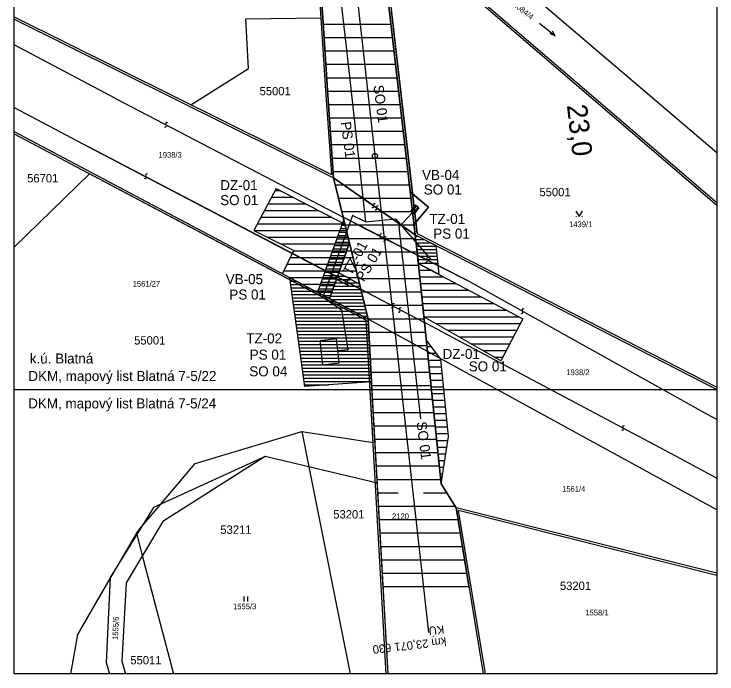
# Model space of a CAD drawing. Extents: x -792659 to -786947, y -1118170 to -1109641.
# Drawn here: x -792658.7 to -792553.7, y -1110542.5 to -1110443.9 of the extents above; entities that cross this region are included whole.
import ezdxf

# ---------------------------------------------------------------- set-up
doc = ezdxf.new("R2010")
doc.units = 0
doc.layers.add('1', color=7, linetype='Continuous')

# ---------------------------------------------------------------- blocks, each defined once
blk = doc.blocks.new('Z31400')
at = {"layer": '1'}
for p, q in [((-1, 1.5), (0, 0)), ((-1, 0), (-0.8, 0)), ((0, 0), (1, 1.5)), ((0.8, 0), (1, 0))]:
    blk.add_line(p, q, dxfattribs=at)
blk = doc.blocks.new('Z8021')
at = {"layer": '1'}
for p, q in [((-3, 0), (3, 0)), ((3, 0), (1.5, 0.5)), ((3, 0), (1.5, -0.5))]:
    blk.add_line(p, q, dxfattribs=at)
blk = doc.blocks.new('Z30602')
at = {"layer": '1'}
for p, q in [((-0.5, 0), (-0.5, 1.5)), ((0.5, 1.5), (0.5, 0))]:
    blk.add_line(p, q, dxfattribs=at)

msp = doc.modelspace()

# ---------------------------------------------------------------- linework, layer by layer
at = {"layer": '1'}
for p, q in [((-792613.96, -1110405.45), (-792608.61, -1110452.76)), ((-792614.67, -1110416.72), (-792612.15, -1110455.3)), ((-792614.37, -1110416.71), (-792611.85, -1110455.28)), ((-792605.76, -1110415.98), (-792598.74, -1110476.89)), ((-792598.74, -1110476.89), (-792605.76, -1110415.98)), ((-792598.74, -1110476.89), (-792605.76, -1110415.98)), ((-792605.39, -1110416.55), (-792598.46, -1110476.7)), ((-792591.51, -1110432.33), (-792553.68, -1110464.6)), ((-792597.93, -1110434.54), (-792553.68, -1110472.43)), ((-792597.68, -1110434.36), (-792553.68, -1110472.03)), ((-792598.46, -1110476.7), (-792602.29, -1110443.46)), ((-792598.46, -1110476.7), (-792602.29, -1110443.46)), ((-792658.68, -1110444.34), (-792611.28, -1110467.89)), ((-792658.68, -1110444.68), (-792610.94, -1110468.39)), ((-792612.47, -1110445.41), (-792602.37, -1110445.41)), ((-792612.34, -1110447.41), (-792602.14, -1110447.41)), ((-792643.45, -1110456.57), (-792658.68, -1110448.5)), ((-792612.2, -1110449.41), (-792601.91, -1110449.41)), ((-792612.07, -1110451.41), (-792601.68, -1110451.41)), ((-792611.94, -1110453.41), (-792601.45, -1110453.41)), ((-792608.61, -1110452.76), (-792606.17, -1110474.95)), ((-792612.15, -1110455.3), (-792611.28, -1110467.89)), ((-792611.85, -1110455.28), (-792610.94, -1110468.39)), ((-792611.8, -1110455.41), (-792601.22, -1110455.41)), ((-792643.45, -1110456.57), (-792609.51, -1110474.26)), ((-792658.68, -1110457.84), (-792647.57, -1110463.72)), ((-792611.67, -1110457.41), (-792600.98, -1110457.41)), ((-792611.54, -1110459.41), (-792600.76, -1110459.41)), ((-792658.68, -1110461.46), (-792605.8, -1110489.46)), ((-792658.68, -1110461.8), (-792606.09, -1110489.65)), ((-792611.41, -1110461.41), (-792605.1, -1110461.41)), ((-792605.73, -1110461.41), (-792600.52, -1110461.41)), ((-792647.57, -1110463.72), (-792608.66, -1110484.08)), ((-792606.89, -1110485.01), (-792647.57, -1110463.72)), ((-792611.27, -1110463.41), (-792600.29, -1110463.41)), ((-792611.14, -1110465.41), (-792600.06, -1110465.41)), ((-792658.68, -1110478.72), (-792647.43, -1110467.76)), ((-792606.09, -1110489.65), (-792647.43, -1110467.76)), ((-792611.01, -1110467.41), (-792599.83, -1110467.41)), ((-792598.74, -1110476.89), (-792610.94, -1110468.39)), ((-792610.94, -1110468.39), (-792609.51, -1110474.26)), ((-792610.94, -1110468.39), (-792598.74, -1110476.89)), ((-792610.94, -1110468.39), (-792609.51, -1110474.26)), ((-792610.69, -1110469.41), (-792599.6, -1110469.41)), ((-792619.53, -1110469.94), (-792622.88, -1110476.25)), ((-792619.7, -1110470.25), (-792618.92, -1110470.25)), ((-792619.53, -1110469.94), (-792609.26, -1110475.29)), ((-792596.78, -1110472.75), (-792599.48, -1110470.49)), ((-792620.23, -1110471.25), (-792617, -1110471.25)), ((-792610.2, -1110471.41), (-792599.37, -1110471.41)), ((-792620.76, -1110472.25), (-792615.09, -1110472.25)), ((-792598.7, -1110472.45), (-792599.47, -1110473.37)), ((-792598.7, -1110472.45), (-792599.47, -1110473.37)), ((-792599.29, -1110472.15), (-792599.29, -1110472.15)), ((-792598.58, -1110472.54), (-792599.22, -1110473.31)), ((-792598.58, -1110472.54), (-792599.22, -1110473.31)), ((-792598.19, -1110472.87), (-792598.7, -1110472.45)), ((-792598.19, -1110472.87), (-792598.7, -1110472.45)), ((-792621.29, -1110473.25), (-792613.17, -1110473.25)), ((-792609.72, -1110473.41), (-792599.14, -1110473.41)), ((-792601.15, -1110475.7), (-792599.22, -1110473.58)), ((-792599.47, -1110473.37), (-792598.96, -1110473.79)), ((-792599.47, -1110473.37), (-792598.96, -1110473.79)), ((-792599.22, -1110473.31), (-792598.95, -1110473.54)), ((-792599.22, -1110473.31), (-792598.95, -1110473.54)), ((-792598.96, -1110473.79), (-792598.19, -1110472.87)), ((-792598.19, -1110472.87), (-792598.96, -1110473.79)), ((-792598.95, -1110473.54), (-792598.31, -1110472.78)), ((-792598.31, -1110472.78), (-792598.95, -1110473.54)), ((-792598.92, -1110475.3), (-792596.78, -1110472.75)), ((-792621.82, -1110474.25), (-792611.25, -1110474.25)), ((-792609.44, -1110474.53), (-792613.35, -1110485.46)), ((-792608.13, -1110474.01), (-792611.42, -1110483.05)), ((-792606.67, -1110475.74), (-792609.51, -1110474.26)), ((-792609.51, -1110474.26), (-792606.89, -1110485.01)), ((-792598.42, -1110479.91), (-792609.51, -1110474.26)), ((-792609.51, -1110474.26), (-792606.89, -1110485.01)), ((-792606.17, -1110474.95), (-792608.13, -1110474.01)), ((-792606.17, -1110474.95), (-792601.71, -1110474.49)), ((-792601.71, -1110474.49), (-792596.44, -1110480.58)), ((-792622.35, -1110475.25), (-792609.33, -1110475.25)), ((-792609.77, -1110475.46), (-792609.21, -1110475.46)), ((-792609.59, -1110474.96), (-792609.33, -1110474.96)), ((-792609.23, -1110475.41), (-792598.91, -1110475.41)), ((-792606.67, -1110475.74), (-792598.42, -1110479.91)), ((-792597.92, -1110504.39), (-792601.15, -1110475.7)), ((-792622.88, -1110476.25), (-792616.88, -1110479.22)), ((-792622.88, -1110476.25), (-792609.03, -1110476.25)), ((-792610.13, -1110476.46), (-792608.97, -1110476.46)), ((-792609.95, -1110475.96), (-792609.09, -1110475.96)), ((-792598.46, -1110476.7), (-792553.68, -1110499.62)), ((-792620.86, -1110477.25), (-792608.78, -1110477.25)), ((-792610.49, -1110477.46), (-792608.73, -1110477.46)), ((-792610.31, -1110476.96), (-792608.85, -1110476.96)), ((-792608.74, -1110477.41), (-792598.69, -1110477.41)), ((-792598.74, -1110476.89), (-792598.42, -1110479.91)), ((-792598.74, -1110476.89), (-792553.68, -1110499.96)), ((-792598.42, -1110479.91), (-792598.74, -1110476.89)), ((-792598.74, -1110476.89), (-792595.67, -1110478.46)), ((-792598.72, -1110477.09), (-792598.35, -1110477.09)), ((-792598.67, -1110477.59), (-792597.37, -1110477.59)), ((-792618.84, -1110478.25), (-792608.54, -1110478.25)), ((-792610.85, -1110478.46), (-792608.72, -1110478.46)), ((-792610.67, -1110477.96), (-792608.6, -1110477.96)), ((-792608.58, -1110478.06), (-792610.18, -1110482.54)), ((-792598.61, -1110478.09), (-792596.39, -1110478.09)), ((-792598.56, -1110478.59), (-792595.66, -1110478.59)), ((-792618.57, -1110482.7), (-792616.88, -1110479.22)), ((-792616.9, -1110479.25), (-792608.3, -1110479.25)), ((-792611.38, -1110479.96), (-792609.26, -1110479.96)), ((-792611.2, -1110479.46), (-792609.08, -1110479.46)), ((-792611.03, -1110478.96), (-792608.9, -1110478.96)), ((-792608.26, -1110479.41), (-792598.48, -1110479.41)), ((-792598.51, -1110479.09), (-792595.6, -1110479.09)), ((-792598.46, -1110479.59), (-792595.55, -1110479.59)), ((-792591.02, -1110483.65), (-792598.42, -1110479.91)), ((-792598.42, -1110479.91), (-792597.37, -1110489.98)), ((-792597.37, -1110489.98), (-792598.42, -1110479.91)), ((-792598.42, -1110479.91), (-792591.02, -1110483.65)), ((-792617.39, -1110480.25), (-792608.05, -1110480.25)), ((-792611.74, -1110480.96), (-792609.61, -1110480.96)), ((-792611.56, -1110480.46), (-792609.44, -1110480.46)), ((-792598.41, -1110480.09), (-792595.49, -1110480.09)), ((-792598.35, -1110480.59), (-792595.44, -1110480.59)), ((-792617.87, -1110481.25), (-792607.81, -1110481.25)), ((-792612.1, -1110481.96), (-792609.97, -1110481.96)), ((-792611.92, -1110481.46), (-792609.79, -1110481.46)), ((-792607.77, -1110481.41), (-792598.27, -1110481.41)), ((-792598.3, -1110481.09), (-792595.38, -1110481.09)), ((-792598.29, -1110481.14), (-792582.67, -1110489.42)), ((-792618.36, -1110482.25), (-792607.57, -1110482.25)), ((-792611.42, -1110483.05), (-792612.54, -1110486.17)), ((-792612.46, -1110482.96), (-792610.33, -1110482.96)), ((-792612.28, -1110482.46), (-792610.15, -1110482.46)), ((-792610.18, -1110482.54), (-792611.56, -1110486.41)), ((-792611.42, -1110483.05), (-792608.74, -1110484.47)), ((-792610.36, -1110483.04), (-792609.27, -1110483.04)), ((-792607.08, -1110484.25), (-792610.18, -1110482.54)), ((-792610.18, -1110482.54), (-792610.18, -1110482.54)), ((-792598.19, -1110482.14), (-792596.4, -1110482.14)), ((-792598.08, -1110483.14), (-792594.51, -1110483.14)), ((-792617.52, -1110483.25), (-792610.43, -1110483.25)), ((-792615.26, -1110499.53), (-792617.47, -1110483.28)), ((-792617.47, -1110483.28), (-792617.47, -1110483.28)), ((-792605.8, -1110489.46), (-792617.47, -1110483.28)), ((-792617.4, -1110483.78), (-792616.53, -1110483.78)), ((-792612.81, -1110483.96), (-792610.69, -1110483.96)), ((-792612.64, -1110483.46), (-792610.51, -1110483.46)), ((-792610.71, -1110484.04), (-792607.46, -1110484.04)), ((-792610.54, -1110483.54), (-792608.37, -1110483.54)), ((-792608.89, -1110483.25), (-792607.32, -1110483.25)), ((-792608.66, -1110484.08), (-792606.89, -1110485.01)), ((-792607.28, -1110483.41), (-792598.06, -1110483.41)), ((-792597.98, -1110484.14), (-792592.63, -1110484.14)), ((-792555.17, -1110503.69), (-792591.02, -1110483.65)), ((-792617.33, -1110484.28), (-792615.58, -1110484.28)), ((-792617.27, -1110484.78), (-792614.64, -1110484.78)), ((-792615.63, -1110484.25), (-792610.79, -1110484.25)), ((-792613.17, -1110484.96), (-792611.04, -1110484.96)), ((-792612.99, -1110484.46), (-792610.86, -1110484.46)), ((-792611.07, -1110485.04), (-792606.89, -1110485.04)), ((-792610.89, -1110484.54), (-792607.01, -1110484.54)), ((-792606.89, -1110485.01), (-792597.37, -1110489.98)), ((-792605.8, -1110489.46), (-792606.89, -1110485.01)), ((-792605.8, -1110489.46), (-792606.89, -1110485.01)), ((-792606.89, -1110485.01), (-792597.37, -1110489.98)), ((-792597.87, -1110485.14), (-792590.75, -1110485.14)), ((-792617.2, -1110485.28), (-792613.69, -1110485.28)), ((-792617.13, -1110485.78), (-792612.75, -1110485.78)), ((-792617.06, -1110486.28), (-792611.81, -1110486.28)), ((-792613.75, -1110485.25), (-792611.15, -1110485.25)), ((-792613.35, -1110485.46), (-792611.22, -1110485.46)), ((-792612.54, -1110486.17), (-792609.77, -1110488.09)), ((-792612.41, -1110485.96), (-792611.4, -1110485.96)), ((-792611.86, -1110486.25), (-792611.5, -1110486.25)), ((-792611.43, -1110486.04), (-792606.64, -1110486.04)), ((-792611.25, -1110485.54), (-792606.76, -1110485.54)), ((-792606.79, -1110485.41), (-792597.85, -1110485.41)), ((-792597.77, -1110486.14), (-792588.86, -1110486.14)), ((-792616.99, -1110486.78), (-792610.86, -1110486.78)), ((-792616.93, -1110487.28), (-792609.92, -1110487.28)), ((-792611.31, -1110486.54), (-792606.52, -1110486.54)), ((-792610.37, -1110487.04), (-792606.4, -1110487.04)), ((-792597.67, -1110487.14), (-792586.98, -1110487.14)), ((-792616.86, -1110487.78), (-792608.97, -1110487.78)), ((-792616.79, -1110488.28), (-792608.03, -1110488.28)), ((-792609.77, -1110488.09), (-792608.83, -1110494.04)), ((-792609.43, -1110487.54), (-792606.27, -1110487.54)), ((-792608.48, -1110488.04), (-792606.15, -1110488.04)), ((-792606.3, -1110487.41), (-792597.64, -1110487.41)), ((-792597.56, -1110488.14), (-792585.09, -1110488.14)), ((-792616.72, -1110488.78), (-792607.08, -1110488.78)), ((-792616.65, -1110489.28), (-792606.14, -1110489.28)), ((-792607.54, -1110488.54), (-792606.03, -1110488.54)), ((-792606.59, -1110489.04), (-792605.9, -1110489.04)), ((-792605.81, -1110489.41), (-792597.43, -1110489.41)), ((-792585.96, -1110495.68), (-792597.46, -1110489.11)), ((-792597.42, -1110489.14), (-792583.21, -1110489.14)), ((-792582.67, -1110489.42), (-792585.96, -1110495.68)), ((-792616.59, -1110489.78), (-792605.78, -1110489.78)), ((-792616.52, -1110490.28), (-792605.75, -1110490.28)), ((-792603.09, -1110542.47), (-792606.09, -1110489.65)), ((-792605.05, -1110507.9), (-792606.09, -1110489.65)), ((-792596.92, -1110494.31), (-792605.8, -1110489.46)), ((-792603.52, -1110529.61), (-792605.8, -1110489.46)), ((-792605.27, -1110498.84), (-792605.8, -1110489.46)), ((-792596.92, -1110494.31), (-792605.8, -1110489.46)), ((-792595.45, -1110490.98), (-792597.37, -1110489.98)), ((-792596.92, -1110494.31), (-792597.37, -1110489.98)), ((-792597.37, -1110489.98), (-792596.92, -1110494.31)), ((-792595.67, -1110490.14), (-792583.04, -1110490.14)), ((-792616.45, -1110490.78), (-792605.72, -1110490.78)), ((-792616.38, -1110491.28), (-792605.7, -1110491.28)), ((-792605.69, -1110491.41), (-792597.22, -1110491.41)), ((-792595.45, -1110490.98), (-792559.11, -1110510.27)), ((-792593.92, -1110491.14), (-792583.57, -1110491.14)), ((-792616.31, -1110491.78), (-792605.67, -1110491.78)), ((-792616.25, -1110492.28), (-792605.64, -1110492.28)), ((-792610.51, -1110492.41), (-792612.99, -1110492.7)), ((-792610.09, -1110495.99), (-792610.51, -1110492.41)), ((-792594.95, -1110495.44), (-792597.1, -1110492.58)), ((-792592.17, -1110492.14), (-792584.1, -1110492.14)), ((-792616.18, -1110492.78), (-792605.61, -1110492.78)), ((-792616.11, -1110493.28), (-792605.58, -1110493.28)), ((-792612.99, -1110492.7), (-792612.58, -1110496.28)), ((-792605.58, -1110493.41), (-792597.01, -1110493.41)), ((-792597, -1110493.58), (-792596.35, -1110493.58)), ((-792590.42, -1110493.14), (-792584.62, -1110493.14)), ((-792616.04, -1110493.78), (-792605.56, -1110493.78)), ((-792615.97, -1110494.28), (-792605.53, -1110494.28)), ((-792608.83, -1110494.04), (-792610.3, -1110494.2)), ((-792594.86, -1110514.07), (-792596.92, -1110494.31)), ((-792553.68, -1110517.97), (-792596.92, -1110494.31)), ((-792596.92, -1110494.31), (-792594.86, -1110514.07)), ((-792596.89, -1110494.58), (-792595.6, -1110494.58)), ((-792588.66, -1110494.14), (-792585.15, -1110494.14)), ((-792615.91, -1110494.78), (-792605.5, -1110494.78)), ((-792615.84, -1110495.28), (-792605.47, -1110495.28)), ((-792605.46, -1110495.41), (-792596.81, -1110495.41)), ((-792596.79, -1110495.58), (-792594.94, -1110495.58)), ((-792593.77, -1110507.02), (-792594.95, -1110495.44)), ((-792586.91, -1110495.14), (-792585.67, -1110495.14)), ((-792615.77, -1110495.78), (-792605.44, -1110495.78)), ((-792615.7, -1110496.28), (-792605.42, -1110496.28)), ((-792615.63, -1110496.78), (-792605.39, -1110496.78)), ((-792612.58, -1110496.28), (-792610.09, -1110495.99)), ((-792596.68, -1110496.58), (-792594.84, -1110496.58)), ((-792615.57, -1110497.28), (-792605.36, -1110497.28)), ((-792615.5, -1110497.78), (-792605.33, -1110497.78)), ((-792605.35, -1110497.41), (-792596.6, -1110497.41)), ((-792596.58, -1110497.58), (-792594.73, -1110497.58)), ((-792615.43, -1110498.28), (-792605.3, -1110498.28)), ((-792615.36, -1110498.78), (-792605.27, -1110498.78)), ((-792605.27, -1110498.84), (-792615.26, -1110499.53)), ((-792602.79, -1110542.47), (-792605.27, -1110498.84)), ((-792596.47, -1110498.58), (-792594.63, -1110498.58)), ((-792615.29, -1110499.28), (-792611.64, -1110499.28)), ((-792605.23, -1110499.41), (-792596.39, -1110499.41)), ((-792596.37, -1110499.58), (-792594.53, -1110499.58)), ((-792658.68, -1110500), (-792553.68, -1110500)), ((-792596.27, -1110500.58), (-792594.43, -1110500.58)), ((-792605.12, -1110501.41), (-792596.18, -1110501.41)), ((-792596.16, -1110501.58), (-792594.33, -1110501.58)), ((-792596.06, -1110502.58), (-792594.22, -1110502.58)), ((-792605.01, -1110503.41), (-792595.97, -1110503.41)), ((-792595.95, -1110503.58), (-792594.12, -1110503.58)), ((-792553.68, -1110504.47), (-792555.17, -1110503.69)), ((-792595.85, -1110504.58), (-792594.02, -1110504.58)), ((-792604.89, -1110505.41), (-792595.76, -1110505.41)), ((-792595.74, -1110505.58), (-792593.92, -1110505.58)), ((-792595.64, -1110506.58), (-792593.82, -1110506.58)), ((-792594.86, -1110514.07), (-792593.77, -1110507.02)), ((-792604.78, -1110507.41), (-792595.55, -1110507.41)), ((-792595.54, -1110507.58), (-792593.86, -1110507.58)), ((-792595.43, -1110508.58), (-792594.01, -1110508.58)), ((-792621.16, -1110509.97), (-792637.83, -1110517.6)), ((-792621.16, -1110509.97), (-792636.48, -1110519.68)), ((-792604.4, -1110513.99), (-792621.16, -1110509.97)), ((-792604.67, -1110509.41), (-792595.35, -1110509.41)), ((-792595.33, -1110509.58), (-792594.17, -1110509.58)), ((-792559.11, -1110510.27), (-792553.68, -1110513.24)), ((-792604.55, -1110511.41), (-792595.14, -1110511.41)), ((-792595.22, -1110510.58), (-792594.32, -1110510.58)), ((-792595.12, -1110511.58), (-792594.48, -1110511.58)), ((-792604.44, -1110513.41), (-792594.93, -1110513.41)), ((-792595.01, -1110512.58), (-792594.63, -1110512.58)), ((-792594.91, -1110513.58), (-792594.79, -1110513.58)), ((-792592.65, -1110517.65), (-792594.86, -1110514.07)), ((-792594.86, -1110514.07), (-792592.65, -1110517.65)), ((-792604.33, -1110515.41), (-792601.31, -1110515.41)), ((-792597.53, -1110515.41), (-792594.03, -1110515.41)), ((-792637.83, -1110517.6), (-792644.34, -1110528.06)), ((-792604.21, -1110517.41), (-792592.8, -1110517.41)), ((-792553.68, -1110527.44), (-792592.65, -1110517.65)), ((-792590.69, -1110529.61), (-792592.65, -1110517.65)), ((-792592.65, -1110517.65), (-792588.58, -1110542.47)), ((-792553.68, -1110527.75), (-792592.28, -1110518.05)), ((-792588.27, -1110542.47), (-792592.28, -1110518.05)), ((-792636.48, -1110519.68), (-792641.95, -1110528.85)), ((-792604.1, -1110519.41), (-792592.36, -1110519.41)), ((-792603.98, -1110521.41), (-792592.03, -1110521.41)), ((-792603.87, -1110523.41), (-792591.71, -1110523.41)), ((-792603.76, -1110525.41), (-792591.38, -1110525.41)), ((-792644.34, -1110528.06), (-792644.9, -1110540.76)), ((-792603.64, -1110527.41), (-792591.05, -1110527.41)), ((-792641.95, -1110528.85), (-792642.58, -1110540.57)), ((-792603.53, -1110529.41), (-792590.72, -1110529.41)), ((-792649.18, -1110536.57), (-792650.23, -1110542.47)), ((-792644.9, -1110540.76), (-792644.42, -1110542.47)), ((-792642.58, -1110540.57), (-792642.01, -1110542.47))]:
    msp.add_line(p, q, dxfattribs=at)
for points in [[(-792658.68, -1110393.97), (-792553.68, -1110393.97), (-792553.68, -1110542.47), (-792658.68, -1110542.47)], [(-792615.31, -1110405.6), (-792606.96, -1110405.48), (-792606.36, -1110410.71), (-792608.74, -1110410.94), (-792608.23, -1110416.1), (-792605.76, -1110415.98), (-792598.74, -1110476.89), (-792597.37, -1110489.98), (-792596.92, -1110494.31), (-792594.86, -1110514.07), (-792592.65, -1110517.65), (-792588.58, -1110542.47), (-792602.79, -1110542.47), (-792605.8, -1110489.46), (-792606.89, -1110485.01), (-792609.51, -1110474.26), (-792610.94, -1110468.39), (-792611.85, -1110455.28), (-792614.37, -1110416.71), (-792614.4, -1110416.41), (-792612.51, -1110416.31), (-792613.01, -1110411.35), (-792614.81, -1110411.53)], [(-792599.48, -1110470.49), (-792596.78, -1110472.75), (-792598.92, -1110475.3)], [(-792609.44, -1110474.53), (-792613.35, -1110485.46), (-792611.56, -1110486.41), (-792610.18, -1110482.54), (-792608.58, -1110478.06)], [(-792598.74, -1110476.89), (-792595.67, -1110478.46), (-792595.21, -1110482.77), (-792598.29, -1110481.14), (-792598.42, -1110479.91)], [(-792610.18, -1110482.54), (-792607.08, -1110484.25), (-792606.89, -1110485.01), (-792605.8, -1110489.46), (-792611.56, -1110486.41)], [(-792615.26, -1110499.53), (-792617.47, -1110483.28), (-792605.8, -1110489.46), (-792605.27, -1110498.84)]]:
    msp.add_lwpolyline(points, close=True, dxfattribs=at)
for points in [[(-792607.94, -1110436.89), (-792605.57, -1110457.95), (-792605.12, -1110461.93), (-792603.37, -1110477.43), (-792602.17, -1110488.16), (-792596.75, -1110536.28)], [(-792632.27, -1110457.46), (-792623.67, -1110452.04), (-792624.04, -1110444.63), (-792612.86, -1110444.48)], [(-792640.41, -1110521.42), (-792639.64, -1110520.51), (-792636.77, -1110517.11), (-792631.64, -1110511.05), (-792615.69, -1110506.27)], [(-792615.69, -1110506.27), (-792605.05, -1110507.9)], [(-792615.69, -1110506.27), (-792614.64, -1110511.53), (-792608.45, -1110542.47)], [(-792640.41, -1110521.42), (-792643.13, -1110526.12), (-792644.35, -1110528.22), (-792649.18, -1110536.57)], [(-792640.41, -1110521.42), (-792640.35, -1110521.65), (-792639.53, -1110524.79), (-792634.88, -1110542.47)]]:
    msp.add_lwpolyline(points, dxfattribs=at)
msp.add_circle((-792604.77, -1110465.1), 0.375, dxfattribs=at)
for centre, start, end in [((-792636.08, -1110460.6), 230.7583, 50.7583), ((-792635.85, -1110460.31), 50.7583, 230.7583), ((-792639.1, -1110468.26), 230.7583, 50.7583), ((-792638.87, -1110467.97), 50.7583, 230.7583), ((-792605.09, -1110472.63), 221.4965, 41.4965), ((-792604.81, -1110472.39), 41.4965, 221.4965), ((-792604.37, -1110472.73), 41.4965, 221.4965), ((-792604.65, -1110472.97), 221.4965, 41.4965), ((-792603.85, -1110476.93), 50.7583, 230.7583), ((-792604.09, -1110477.22), 230.7583, 50.7583), ((-792603.39, -1110477.66), 230.7583, 50.7583), ((-792603.16, -1110477.37), 50.7583, 230.7583), ((-792597.1, -1110480.76), 230.7583, 50.7583), ((-792596.87, -1110480.47), 50.7583, 230.7583), ((-792611.42, -1110482.88), 230.7583, 50.7583), ((-792611.19, -1110482.59), 50.7583, 230.7583), ((-792608.94, -1110484.13), 230.7583, 50.7583), ((-792608.71, -1110483.84), 50.7583, 230.7583), ((-792601.97, -1110487.33), 50.7583, 230.7583), ((-792602.2, -1110487.62), 230.7583, 50.7583), ((-792601.19, -1110488.24), 230.7583, 50.7583), ((-792600.95, -1110487.95), 50.7583, 230.7583), ((-792582.84, -1110488.43), 230.7583, 50.7583), ((-792582.61, -1110488.14), 50.7583, 230.7583), ((-792567.82, -1110505.88), 230.7583, 50.7583), ((-792567.59, -1110505.59), 50.7583, 230.7583)]:
    msp.add_arc(centre, 0.188, start, end, dxfattribs=at)

# ---------------------------------------------------------------- block references
at = {"layer": '1', "xscale": 0.5, "yscale": 0.5, "rotation": -38.83710000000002}
msp.add_blockref('Z8021', (-792579.01, -1110446.2), dxfattribs=at)
at = {"layer": '1', "xscale": 0.5, "yscale": 0.5}
for name, p in [('Z31400', (-792574.26, -1110474.12)), ('Z30602', (-792624.05, -1110531.63))]:
    msp.add_blockref(name, p, dxfattribs=at)

# ---------------------------------------------------------------- texts
at = {"layer": '1'}
for s, height, rotation, p in [('2084/4', 0.85, 321.3139, (-792584.21, -1110442.62)), ('SO 01', 1.5, 277.3895, (-792605, -1110454.6)), ('23,0', 3, 276.4179, (-792576.1, -1110457.53)), ('PS 01', 1.5, 277.3895, (-792609.87, -1110460.07)), ('TZ-01', 1.5, 62.0284, (-792608.32, -1110483.07)), ('PS 01', 1.5, 59.4008, (-792606.42, -1110483.99)), ('SO 01', 1.5, 277.3895, (-792598.57, -1110504.88)), ('1555/6', 0.85, 87.8958, (-792643.15, -1110537.4)), ('KÚ', 1.25, 186.0649, (-792594.49, -1110535.21)), ('km 23,071 630', 1.25, 186.4259, (-792594.18, -1110536.99))]:
    msp.add_text(s, height=height, rotation=rotation, dxfattribs=at).set_placement(p)
for s, height, p in [('55001', 1.25, (-792622, -1110456.04)), ('1938/3', 0.85, (-792637.1, -1110465.37)), ('VB-04', 1.5, (-792597.73, -1110468.69)), ('56701', 1.25, (-792656.72, -1110469.05)), ('DZ-01', 1.5, (-792627.87, -1110470.21)), ('SO 01', 1.5, (-792597.47, -1110470.87)), ('55001', 1.25, (-792580.19, -1110471.12)), ('SO 01', 1.5, (-792627.89, -1110472.45)), ('TZ-01', 1.5, (-792596.64, -1110475.26)), ('1439/1', 0.85, (-792575.77, -1110475.73)), ('PS 01', 1.5, (-792596.06, -1110477.45)), ('VB-05', 1.5, (-792627.06, -1110484.25)), ('1561/27', 0.85, (-792640.96, -1110484.62)), ('PS 01', 1.5, (-792626.52, -1110486.55)), ('55001', 1.25, (-792640.74, -1110493.27)), ('TZ-02', 1.5, (-792623.99, -1110493.1)), ('k.ú. Blatná', 1.5, (-792656.33, -1110496.1)), ('PS 01', 1.5, (-792623.48, -1110495.53)), ('DZ-01', 1.5, (-792594.66, -1110495.42)), ('SO 04', 1.5, (-792623.54, -1110498.02)), ('SO 01', 1.5, (-792590.76, -1110497.28)), ('DKM, mapový list Blatná 7-5/22', 1.5, (-792656.54, -1110498.72)), ('1938/2', 0.85, (-792576.18, -1110497.84)), ('DKM, mapový list Blatná 7-5/24', 1.5, (-792656.57, -1110502.81)), ('1561/4', 0.85, (-792576.81, -1110515.26)), ('53201', 1.25, (-792610.99, -1110519.25)), ('2120', 0.85, (-792602.22, -1110519.35)), ('53211', 1.25, (-792627.86, -1110521.54)), ('53201', 1.25, (-792577.13, -1110529.93)), ('1555/3', 0.85, (-792625.97, -1110532.81)), ('1558/1', 0.85, (-792573.34, -1110533.73)), ('55011', 1.25, (-792641.31, -1110541.04))]:
    msp.add_text(s, height=height, dxfattribs=at).set_placement(p)

doc.saveas('drawing.dxf')
